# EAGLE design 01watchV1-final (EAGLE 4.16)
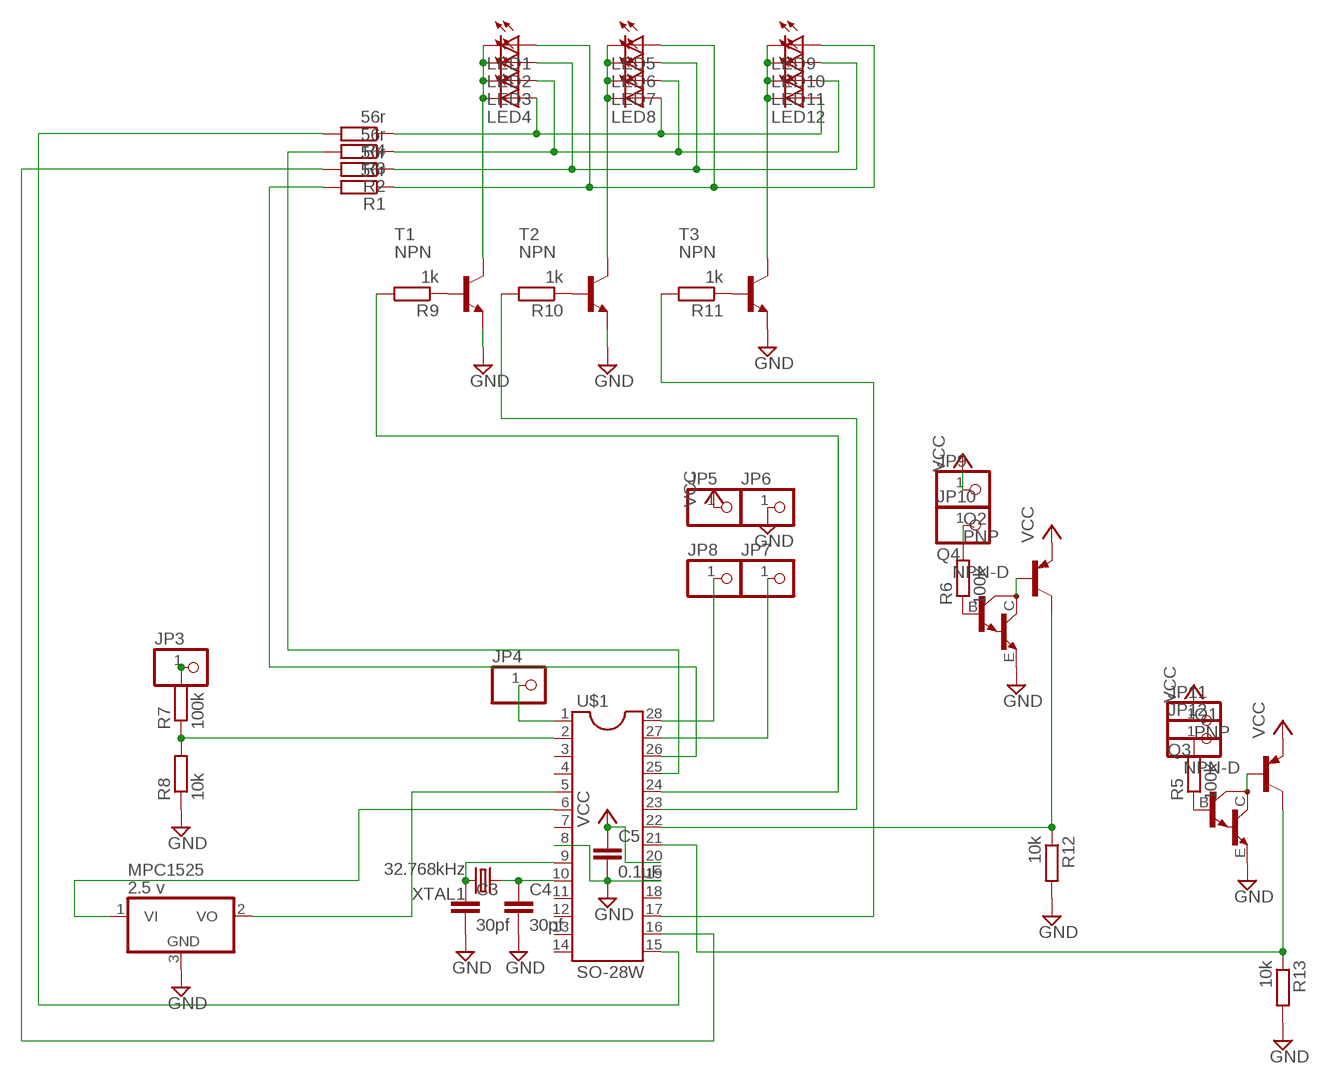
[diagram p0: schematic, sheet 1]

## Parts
C3  30pf  C-EUC1206  [C1206]
C4  30pf  C-EUC1206  [C1206]
C5  0.1uF  C-EUC1206  [C1206]
JP3  PINHD-1X1  [1X01]
JP4  PINHD-1X1  [1X01]
JP5  PINHD-1X1  [1X01]
JP6  PINHD-1X1  [1X01]
JP7  PINHD-1X1  [1X01]
JP8  PINHD-1X1  [1X01]
JP9  PINHD-1X1  [1X01]
JP10  PINHD-1X1  [1X01]
JP11  PINHD-1X1  [1X01]
JP12  PINHD-1X1  [1X01]
LED1  LEDCHIPLED_1206  [CHIPLED_1206]
LED2  LEDCHIPLED_1206  [CHIPLED_1206]
LED3  LEDCHIPLED_1206  [CHIPLED_1206]
LED4  LEDCHIPLED_1206  [CHIPLED_1206]
LED5  LEDCHIPLED_1206  [CHIPLED_1206]
LED6  LEDCHIPLED_1206  [CHIPLED_1206]
LED7  LEDCHIPLED_1206  [CHIPLED_1206]
LED8  LEDCHIPLED_1206  [CHIPLED_1206]
LED9  LEDCHIPLED_1206  [CHIPLED_1206]
LED10  LEDCHIPLED_1206  [CHIPLED_1206]
LED11  LEDCHIPLED_1206  [CHIPLED_1206]
LED12  LEDCHIPLED_1206  [CHIPLED_1206]
MPC1525  2.5 v  MCP1525-SOT23  [SOT23-3]
Q1  PNP  MMBT3640LT1SMD  [SOT23-BEC]
Q2  PNP  MMBT3640LT1SMD  [SOT23-BEC]
Q3  NPN-D  MMBTA14LT1  [SOT23-BEC]
Q4  NPN-D  MMBTA14LT1  [SOT23-BEC]
R1  56r  R-EU_M1206  [M1206]
R2  56r  R-EU_M1206  [M1206]
R3  56r  R-EU_M1206  [M1206]
R4  56r  R-EU_M1206  [M1206]
R5  100k  R-EU_M1206  [M1206]
R6  100k  R-EU_M1206  [M1206]
R7  100k  R-EU_R1206  [R1206]
R8  10k  R-EU_R1206  [R1206]
R9  1k  R-EU_M1206  [M1206]
R10  1k  R-EU_M1206  [M1206]
R11  1k  R-EU_M1206  [M1206]
R12  10k  R-EU_M1206  [M1206]
R13  10k  R-EU_M1206  [M1206]
T1  NPN  BCX70SMD  [SOT23]
T2  NPN  BCX70SMD  [SOT23]
T3  NPN  BCX70SMD  [SOT23]
U$1  SO-28W  [SO-28W]
XTAL1  32.768kHz  CRYTALTC26H  [TC26H]

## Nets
GND: C3.2 C4.2 C5.2 JP6.1 MPC1525.3(GND) Q3.E Q4.E R8.1 R12.2 R13.2 T1.2(E) T2.2(E) T3.2(E) U$1.8 U$1.19
N$1: JP8.1 U$1.28
N$2: Q1.C R13.1 U$1.21
N$3: R9.2 U$1.24
N$4: LED4.A LED8.A LED12.A R4.1
N$5: LED5.C LED6.C LED7.C LED8.C T2.3(C)
N$6: R1.2 U$1.26
N$7: MPC1525.1(VI) U$1.6
N$8: R3.2 U$1.25
N$9: LED9.C LED10.C LED11.C LED12.C T3.3(C)
N$10: LED1.C LED2.C LED3.C LED4.C T1.3(C)
N$11: LED3.A LED7.A LED11.A R3.1
N$12: LED2.A LED6.A LED10.A R2.1
N$13: Q1.B Q3.C
N$14: Q2.B Q4.C
N$15: JP10.1 R6.2
N$16: Q4.B R6.1
N$17: JP12.1 R5.2
N$18: Q3.B R5.1
N$19: JP4.1 U$1.1
N$20: LED1.A LED5.A LED9.A R1.1
N$25: JP7.1 U$1.27
N$26: R11.2 U$1.17
N$27: R10.2 U$1.23
N$28: R4.2 U$1.15
N$29: Q2.C R12.1 U$1.22
N$30: R2.2 U$1.16
N$31: R9.1 T1.1(B)
N$32: R10.1 T2.1(B)
N$33: R11.1 T3.1(B)
N$39: C4.1 U$1.10 XTAL1.1
N$40: C3.1 U$1.9 XTAL1.2
N$44: R7.1 R8.2 U$1.2
N$47: JP3.1 R7.2
N$48: MPC1525.2(VO) U$1.5
VCC: C5.1 JP5.1 JP9.1 JP11.1 Q1.E Q2.E U$1.20
Unconnected: U$1.3 U$1.4 U$1.7 U$1.11 U$1.12 U$1.13 U$1.14 U$1.18

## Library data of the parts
C3-C5 = rcl:C-EU: CAPACITOR, European symbol
JP3-JP12 = pinhead:PINHD-1X1: PIN HEADER
LED1-LED12 = led:LED: LED
MPC1525 = iPodSMPS:MCP1525-SOT23
Q1 Q2 = transistor-pnp:MMBT3640*: PNP Transistror
Q3 Q4 = transistor-npn:MMBTA14*: NPN Darlington Transistor
R1-R13 = rcl:R-EU_: RESISTOR, European symbol
T1-T3 = transistor:BCX70SMD: NPN TRANSISTOR
U$1 = SO-pads:SO-28W
XTAL1 = crystal:CRYTAL: CRYSTAL

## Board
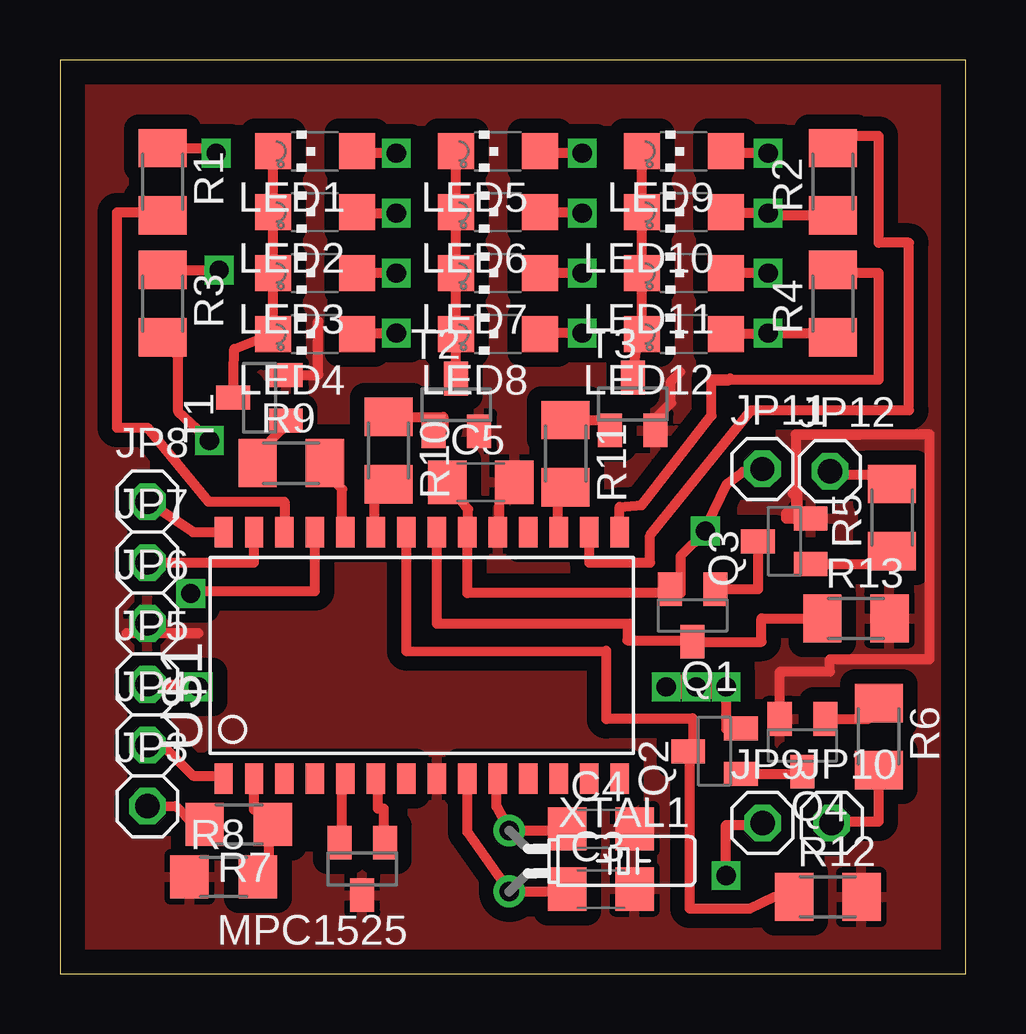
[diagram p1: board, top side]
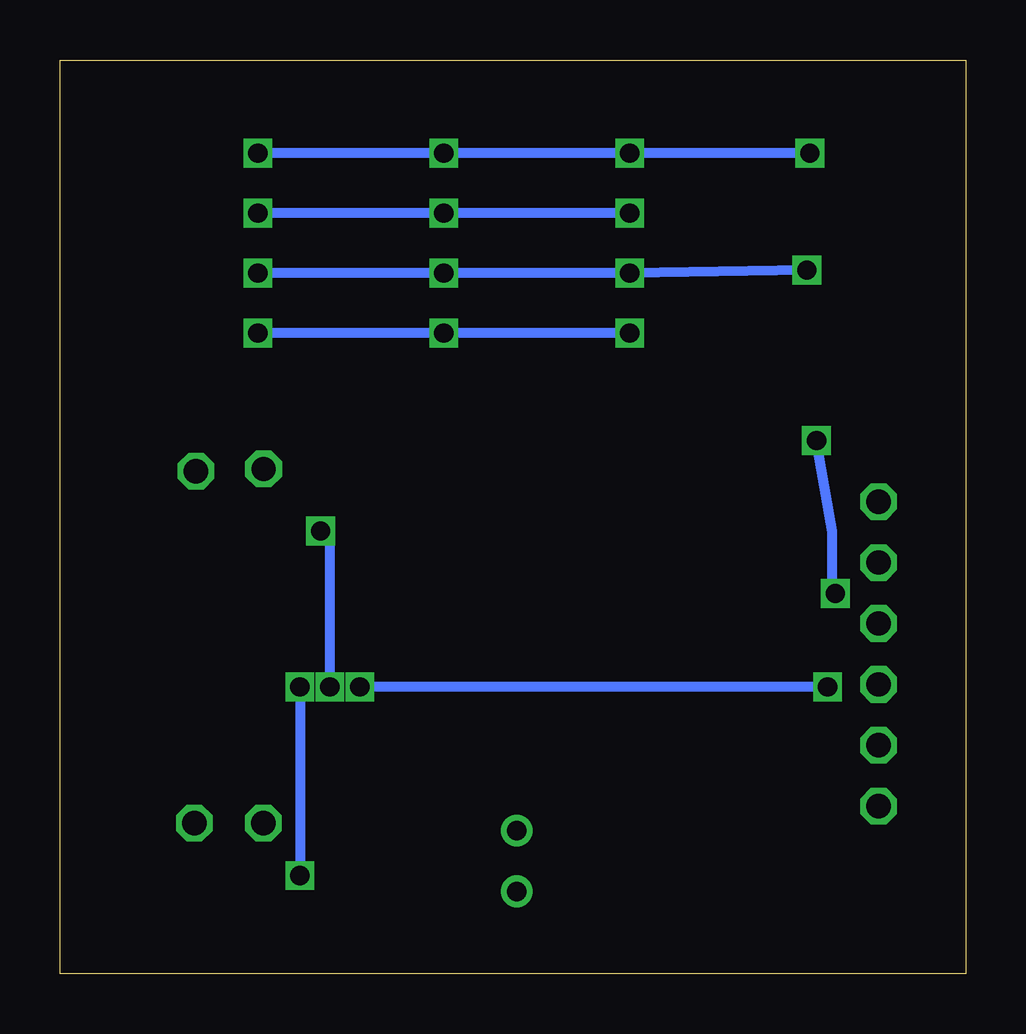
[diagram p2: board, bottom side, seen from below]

Size 37.77 x 38.09 mm. Coordinates in mm from the lower left corner, seen from the top.
Outline: 0,0 37.77,0 37.77,38.09 0,38.09 0,0
Copper layers (1*16): Top 0.035mm / dielectric 1.5mm / Bottom 0.035mm
Design rules "10mils": minimum track width 10mil, minimum drill 24mil, track to track 10mil, track to pad 10mil, pad to pad 10mil, via to via 10mil, smd to smd 10mil, copper to edge 40mil, drill to drill 10mil, minimum pad ring 10mil, minimum via ring 8mil, stop-mask expansion 0mil, vias tented up to drill 0mil, thermal gap 10mil

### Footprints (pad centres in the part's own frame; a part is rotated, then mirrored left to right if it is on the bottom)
C1206 = smd 1.6 x 1.8: 1 -1.4,0; 2 1.4,0
1X01 = drill 1.016 octagon: 1 0,0
CHIPLED_1206 = smd 1.5 x 1.5: A 0,-1.75; C 0,1.75
SOT23-3 = smd 1 x 1.4: 1 -0.95,-1.1; 2 0.95,-1.1; 3 0,1.1
SOT23-BEC = smd 1 x 1.4: B -0.95,-1.1; C 0,1.1; E 0.95,-1.1
M1206 = smd 1.6 x 2: 1 -1.4,0; 2 1.4,0
R1206 = smd 1.6 x 1.803: 1 -1.422,0; 2 1.422,0
SOT23 = smd 1 x 1.4: 1 -0.95,-1.1; 2 0.95,-1.1; 3 0,1.1
SO-28W = smd 0.762 x 1.27: 1 -7.62,-5.207; 2 -6.35,-5.207; 3 -5.08,-5.207; 4 -3.81,-5.207; 5 -2.54,-5.207; 6 -1.27,-5.207; 7 0,-5.207; 8 1.27,-5.207; 9 2.54,-5.207; 10 3.81,-5.207; 11 5.08,-5.207; 12 6.35,-5.207; 13 7.62,-5.207; 14 8.89,-5.207; 15 8.89,5.08; 16 7.62,5.08; 17 6.35,5.08; 18 5.08,5.08; 19 3.81,5.08; 20 2.54,5.08; 21 1.27,5.08; 22 0,5.08; 23 -1.27,5.08; 24 -2.54,5.08; 25 -3.81,5.08; 26 -5.08,5.08; 27 -6.35,5.08; 28 -7.62,5.08
TC26H = drill 0.813 round: 1 -1.27,0; 2 1.27,0

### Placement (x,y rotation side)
C3  22.55,3.53 0 top
C4  22.55,6.04 0 top
C5  17.54,20.49 0 top
JP3  3.64,6.98 0 top
JP4  3.64,9.52 0 top
JP5  3.64,12.06 0 top
JP6  3.64,14.6 0 top
JP7  3.64,17.14 0 top
JP8  3.64,19.68 0 top
JP9  29.29,6.28 0 top
JP10  32.17,6.28 0 top
JP11  29.28,21.04 0 top
JP12  32.1,20.95 0 top
LED1  10.63,34.28 90 top
LED2  10.63,31.75 90 top
LED3  10.63,29.21 90 top
LED4  10.63,26.67 90 top
LED5  18.25,34.28 90 top
LED6  18.25,31.75 90 top
LED7  18.25,29.21 90 top
LED8  18.25,26.67 90 top
LED9  26,34.28 90 top
LED10  26,31.75 90 top
LED11  26,29.21 90 top
LED12  26,26.67 90 top
MPC1525  12.6,4.37 180 top
Q1  26.37,14.93 180 top
Q2  27.29,9.27 90 top
Q3  30.19,18.02 90 top
Q4  30.95,9.52 180 top
R1  4.28,33.02 270 top
R2  32.22,33.02 90 top
R3  4.28,27.93 270 top
R4  32.22,27.93 90 top
R5  34.69,19.02 90 top
R6  34.12,9.88 270 top
R7  7.45,6.23 180 top
R8  6.82,4.04 0 top
R9  9.64,21.28 0 top
R10  13.7,21.81 270 top
R11  21.08,21.68 270 top
R12  32.01,3.2 0 top
R13  33.18,14.81 0 top
T1  8.32,24.01 90 top
T2  16.52,23.71 0 top
T3  23.88,23.75 0 top
U$1  14.44,13.33 0 top
XTAL1  18.73,4.7 270 top

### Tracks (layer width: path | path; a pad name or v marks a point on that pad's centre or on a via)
GND
  Top 0.406: 30.54,20.01 30.67,20.01 30.67,22.48 | 30.67,22.48 33.4,22.48 | 30.67,18.97 30.28,18.97 | 30.67,22.48 30.67,18.97 | 30.67,22.48 36.26,22.48 36.26,13.12 32.1,13.12 32.1,12.6 30.02,12.6 30.02,10.62 | 30.02,10.62 30.02,10.52 | Q4.E 30.02,10.62 | 30.67,18.97 30.77,18.97 30.77,19.2 | 30.77,19.2 30.77,20.2 | 30.28,18.97 Q3.E | 30.77,19.2 30.28,19.2 30.28,18.97 | 18.32,18.41 18.32,18.32 | U$1.19 18.32,18.41 | C5.2 18.32,19.62 18.32,18.41 | T1.2 10.77,24.96 10.77,27.2 | T3.2 24.83,23.14 25.47,23.78 25.47,24.69 25.86,25.08 | 2.77,14.2 5.77,14.2
  pour Top (isolate 0.61): 0.47,-0.64 37.3,-0.64 37.3,38.73 0.47,38.73
N$1
  Top 0.406: JP8.1 5.55,18.41 U$1.28
N$2
  Top 0.406: U$1.21 15.71,14.6 23.65,14.6 | 31.77,15.2 R13.1 29.24,14.81 29.24,13.84 Q1.C 26.38,13.9 23.65,13.9 23.65,14.6 | 23.65,14.6 23.77,14.6
N$3
  Top 0.406: R9.2 11.43,20.54 11.77,20.2 11.77,18.2 11.9,18.33 U$1.24
N$4  (via drill 0.8)
  Top 0.254: 27.77,26.7 27.93,26.54 | v29.52,26.7 29.74,26.67 | 19.77,26.7 19.8,26.67 LED8.A
  Top 0.406: v21.77,26.7 19.77,26.7 | LED4.A 12.48,26.67 12.52,26.7 v14.02,26.7 | LED12.A 27.75,26.68 27.77,26.7 27.8,26.67 29.74,26.67 | R4.1 32.11,26.54 32.02,26.45 31.77,26.7 v29.52,26.7
  Bottom 0.406: v29.52,26.7 v21.77,26.7 v14.02,26.7
N$5
  Top 0.406: LED5.C 16.5,31.9 16.34,31.75 LED6.C 16.5,29.36 16.34,29.21 LED7.C 16.5,26.82 16.34,26.67 LED8.C 16.5,24.81 T2.3
N$6
  Top 0.406: U$1.26 9.36,19.68 6.18,19.68 3.64,22.76 2.38,22.76 2.38,31.75 4.28,31.75 R1.2
N$7
  Top 0.406: U$1.6 13.25,8.12 13.25,6.88 13.51,6.88 13.51,5.73 | 13.51,5.73 13.51,5.71 | MPC1525.1 13.51,5.73
N$8  (via drill 0.8)
  Top 0.406: U$1.25 10.63,15.95 5.32,15.95 5.32,15.98 5.45,16.11 v5.45,15.85 | 4.28,26.67 R3.2 4.28,26.38 4.93,25.73 4.93,23.43 v6.23,22.22
  Bottom 0.406: v6.23,22.22 5.58,18.43 5.58,15.98 v5.45,15.85
N$9
  Top 0.406: T3.3 24.1,26.67 LED12.C 24.25,29.05 24.1,29.21 LED11.C 24.25,31.59 24.1,31.75 LED10.C 24.25,34.13 24.1,34.28 LED9.C
N$10
  Top 0.406: 9.36,26.67 LED4.C 8.83,26.67 | LED1.C 8.88,31.9 8.72,31.75 LED2.C 8.88,29.36 8.72,29.21 LED3.C 8.88,26.82 8.72,26.67 8.83,26.67 | T1.3 7.27,26.04 8.83,26.67
N$11  (via drill 0.8)
  Top 0.254: 6.66,29.33 v6.64,29.33 | 12.52,29.2 12.52,29.21 LED3.A | 19.77,29.2 19.78,29.21 LED7.A | 27.27,29.2 27.28,29.21 LED11.A
  Top 0.406: R3.1 6.66,29.33 | v14.02,29.2 12.52,29.2 | v21.77,29.2 19.77,29.2 | v29.52,29.2 27.27,29.2
  Bottom 0.406: v6.64,29.33 v14.02,29.2 v21.77,29.2 v29.52,29.2
N$12  (via drill 0.8)
  Top 0.254: v29.52,31.7 29.61,31.61 | 20,31.72 20.02,31.7 v21.77,31.7 21.75,31.72 | 28.02,31.7 27.97,31.75 LED10.A | 12.27,31.7 12.32,31.75 LED2.A
  Top 0.406: 29.61,31.61 R2.1 | LED6.A 20,31.72 21.75,31.72 | v29.52,31.7 28.02,31.7 | 12.27,31.7 v14.02,31.7
  Bottom 0.406: v29.52,31.7 v21.77,31.7 v14.02,31.7
N$13
  Top 0.406: Q3.C 29.11,18.02 29.11,16.04 Q1.B
N$14
  Top 0.406: 30.77,8.32 30.77,8.42 Q4.C | Q2.B 30.77,8.32 | 30.77,8.32 30.77,8.2
N$15
  Top 0.406: R6.2 34.12,6.34 31.92,6.34 31.85,6.28 | 31.85,6.28 31.77,6.2 | JP10.1 31.85,6.28
N$16
  Top 0.406: R6.1 34.12,11.15 33.66,10.62 Q4.B
N$17
  Top 0.406: JP12.1 32.62,20.95 32.62,20.8 34.05,20.8 35.05,19.9 R5.2
N$18
  Top 0.406: 34.69,17.65 34.7,17.67 | 34.69,17.65 R5.1 | Q3.B 34.11,17.07 34.69,17.65
N$19
  Top 0.406: JP4.1 4.28,9.52 5.55,8.25 6.82,8.25 U$1.1
N$20  (via drill 0.8)
  Top 0.254: 6.55,34.42 v6.51,34.2 | 12.27,34.2 12.36,34.28 LED1.A | 20.27,34.2 20.18,34.28 LED5.A | 27.27,34.2 27.36,34.28 LED9.A
  Top 0.406: R1.1 6.55,34.42 | v14.02,34.2 12.27,34.2 | v21.77,34.2 20.27,34.2 | v29.52,34.2 27.27,34.2
  Bottom 0.406: v6.51,34.2 v14.02,34.2 v21.77,34.2 v29.52,34.2
N$25
  Top 0.406: U$1.27 8.09,17.14 JP7.1
N$26
  Top 0.406: R11.2 20.77,20.28 20.77,18.41 U$1.17
N$27
  Top 0.406: U$1.23 13.12,18.41 13.12,20.4 13.64,20.41 R10.2
N$28
  Top 0.406: R4.2 32.22,29.21 34.12,29.21 34.12,24.76 27.94,24.76 | 27.94,24.76 27.14,24.76 | U$1.15 23.33,19.46 24.26,19.53 27.16,23.26 27.16,24.72 27.84,24.72 27.94,24.82 27.94,24.76
N$29
  Top 0.406: U$1.22 14.44,13.44 22.77,13.46 22.77,10.62 22.87,10.65 26.38,10.65 26.38,9.61 | R12.1 29.77,3.2 28.77,2.72 26.25,2.72 26.25,9.22 26.38,9.22 26.38,9.61 | Q2.C 26.18,9.41 26.38,9.61
N$30
  Top 0.406: 32.22,34.92 32.86,34.92 32.22,34.28 | U$1.16 22.06,17.14 24.6,17.14 24.6,18.27 28.82,23.49 35.39,23.49 35.39,30.47 34.12,30.47 34.12,34.92 32.22,34.92 | 32.22,34.28 R2.2 | 32.22,34.92 32.22,34.28
N$31
  Top 0.406: T1.1 9.63,23.06 8.77,22.2 8.77,21.2 8.72,21.15 R9.1
N$32
  Top 0.406: 15.98,22.87 15.98,22.74 | 15.98,22.87 T2.1 | R10.1 15.98,23.21 15.98,22.87
N$33
  Top 0.406: 23.13,22.65 23.13,22.61 | 23.13,22.65 T3.1 | R11.1 23.13,23.08 23.13,22.65
N$39
  Top 0.406: 18.25,8.25 U$1.10 18.19,8.12 18.19,6.97 XTAL1.1 21.18,5.97 21.18,6.04 | 21.18,6.04 21.18,6.1 | 21.18,6.04 C4.1
N$40
  Top 0.406: 16.98,8.25 U$1.9 16.98,5.91 XTAL1.2 21.18,3.43 21.18,3.53 C3.1
N$44
  Top 0.406: R8.2 8.72,4.17 8.72,5.71 R7.1 8.88,6.19 8.09,6.85 U$1.2 8.09,8.25
N$47
  Top 0.406: JP3.1 4.82,7 5.58,6.23 R7.2 6.18,5.71
N$48
  Top 0.406: 11.9,8.25 U$1.5 11.77,8.12 | 11.77,8.12 11.77,8.2 | MPC1525.2 11.77,5.73 11.77,8.12
VCC  (via drill 0.8)
  Top 0.406: 26.89,18.41 26.98,18.72 27.81,20.41 28.46,20.92 29.24,20.92 29.24,21.04 JP11.1 | 26.89,18.41 25.87,17.41 25.87,16.2 | 25.87,16.2 25.87,15.87 16.98,15.87 U$1.20 17.02,18.41 | 27.78,12.06 27.78,12.2 | JP5.1 5.63,12.06 v5.77,11.95 | v27.77,4.09 27.77,6.2 28.98,6.2 28.98,6.28 JP9.1 | 27.77,10.22 27.77,10.2 | 27.77,10.22 Q2.E | v27.77,11.95 27.77,10.22 | 25.87,16.2 25.77,16.2 25.77,16.04 Q1.E | 17.02,18.41 17.02,18.32 | C5.1 17.02,19.36 17.02,18.41 | 26.86,18.41 v26.9,18.45 v26.91,18.45 | 26.86,18.41 26.89,18.41 | 26.86,18.41 26.77,18.32
  Top 1.016: v25.27,11.95 v26.51,11.95 | v27.77,11.95 v26.52,11.95 v26.51,11.95 | v26.51,11.95 v27.77,11.95 | 27.78,12.06 27.78,11.98 27.81,11.95 v27.77,11.95
  Bottom 0.406: v27.77,11.95 v27.77,4.09 | v5.77,11.95 v25.27,11.95 | v26.91,18.45 v26.9,18.45 26.52,18.07 v26.52,11.95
